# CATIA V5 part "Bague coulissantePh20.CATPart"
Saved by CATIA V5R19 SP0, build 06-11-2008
Part number: Bague coulissante
Bounding box of the stored display mesh (mm): x -22.5 to 22.5, y -22.5 to 22.5, z 0 to 25
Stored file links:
  C:\Users\Laurent\Desktop\Sujet Bac national\Sujet National E33\CFAO Catia\Bague coulissantePh20.CATPart
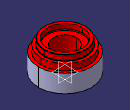
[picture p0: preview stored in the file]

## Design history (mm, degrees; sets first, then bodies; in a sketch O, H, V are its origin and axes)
Body1 (main body)
  Sketch1 on xy-plane, origin (0, 0, 0), H (1, 0, 0), V (0, 1, 0)
    circle A1 centre (0, 0) radius 22.5
    radius A1 = 22.5
  Pad1: profile Sketch1, direction (0, 0, 1), length 25
  Sketch2 on end face of Pad1, origin (0, 0, 25), H (1, 0, 0), V (0, 1, 0)
    circle A1 centre (0, 0) radius 17.45
    radius A1 = 17.45
  Pocket1: profile Sketch2, direction (0, 0, -1), length 4.78, outer side
  Sketch3 on end face of Pad1, origin (0, 0, 25), H (1, 0, 0), V (0, 1, 0)
    circle A1 centre (0, 0) radius 20
    radius A1 = 20
  Pocket2: profile Sketch3, direction (0, 0, -1), length 10, outer side
  Sketch4 on end face of Pad1, origin (0, 0, 25), H (1, 0, 0), V (0, 1, 0)
    circle A1 centre (0, 0) radius 10
    radius A1 = 10
  Pocket3: profile Sketch4, direction (0, 0, -1), through (limit type 3)
  Sketch5 on end face of Pad1, origin (0, 0, 25), H (1, 0, 0), V (0, 1, 0)
    circle A1 centre (0, 0) radius 14.95
    radius A1 = 14.95
  Pocket4: profile Sketch5, direction (0, 0, -1), length 4.78
  Sketch6 on zx-plane, origin (0, 0, 0), H (-1, 0, 0), V (0, 0, 1)
    axis line L1 (-25.6583, 20.6) -> (32.7674, 20.6)
    arc A1 centre (14.79, 20.6) radius 0.5 from (14.79, 20.1) to (14.79, 21.1) ccw
    point P3 (14.79, 20.6)
    reference projected line E1 (-17.45, 25) -> (17.45, 25) from edge [face of Pocket1 from Sketch2.A1 | end face of Pad1]
    line L2 (14.79, 20.1) -> (0, 20.1)
    point P4 (0, 20.1)
    line L3 (14.79, 21.1) -> (0, 21.1)
    point P5 (0, 21.1)
    line L4 (0, 20.1) -> (0, 21.1)
    reference projected line E2 through (0, 0) direction (0, 1) from axis of face of Pocket1 from Sketch2.A1
    distance L1 E1 = 4.4
    radius A1 = 0.5
    distance A1 E2 = 15.29
    horizontal: L1 H, L2 H, L3 H
    coincidence: P3 L1, P4 V, P5 V
    tangency: L3 A1, L2 A1
    vertical: L4 V
  Groove1: profile Sketch6, axis axis of face of Pocket2 from Sketch3.A1, angle 360
  Fillet1: radius 0.3, on edge [face of Pocket1 from Sketch2.A1 | end face of Pad1]; edge [end face of Pocket1 | face of Pocket1 from Sketch2.A1]
  Sketch7 on start face of Pad1, origin (0, 0, 0), H (1, 0, 0), V (0, -1, 0)
    circle A1 centre (0, 0) radius 23.7695
  Pocket5: profile Sketch7, direction (0, 0, 1), length 1.42, deactivated
  Sketch8 on end face of Pocket5, origin (0, 0, 1.42), H (1, 0, 0), V (0, -1, 0)
    circle A1 centre (0, 0) radius 17.9915
    radius A1 = 17.9915
  Pocket6: profile Sketch8, direction (0, 0, 1), length 14.8, outer side, deactivated
  Sketch9 on end face of Pocket5, origin (0, 0, 1.42), H (1, 0, 0), V (0, -1, 0)
    circle A1 centre (0, 0) radius 16.5
    radius A1 = 16.5
  Pocket7: profile Sketch9, direction (0, 0, 1), length 6.8, outer side, deactivated
  Chamfer1: length 1.5, angle 45, on edge [face of Pocket7 from Sketch9.A1 | end face of Pocket5], deactivated
  Sketch10 on zx-plane, origin (0, 0, 0), H (-1, 0, 0), V (0, 0, 1)
    line L1 (15.5, 8.22) -> (15.5, 6.72)
    line L2 (15.5, 6.72) -> (31.9529, 6.72)
    line L3 (15.5, 8.22) -> (31.9529, 8.22)
    line L4 (31.9529, 8.22) -> (31.9529, 6.72)
    reference projected line E1 (14.5, 1.42) -> (-14.5, 1.42) from edge [face of Chamfer1 | end face of Pocket5]
    reference projected line E2 through (0, 0) direction (0, -1) from axis of face of Pocket7 from Sketch9.A1
    distance L3 E1 = 6.8
    distance L1 E2 = 15.5
    distance L3 L2 = 1.5
    vertical: L1 V, L4 V
    horizontal: L2 H, L3 H
  Groove2: profile Sketch10, axis axis of face of Chamfer1, angle 360, deactivated
  Fillet2: radius 0.5, on edge [face of Groove2 from Sketch10.L1 | face of Groove2]; edge [face of Groove2 from Sketch10.L2 | face of Groove2 from Sketch10.L1], deactivated
  Sketch11 on end face of Pocket5, origin (0, 0, 1.42), H (1, 0, 0), V (0, -1, 0)
    circle A1 centre (0, 0) radius 14.2912
    radius A1 = 14.2912
  Pocket8: profile Sketch11, direction (0, 0, -1), through (limit type 3), deactivated
  Chamfer2: length 0.9, angle 30, on edge [end face of Pocket5 | face of Pocket8 from Sketch11.A1], deactivated
  Plane1: type Offset, Offset 19, RefPlane yz-plane
  Sketch12 on Plane1, origin (19, 0, 0), H (0, 1, 0), V (0, 0, 1)
    line L1 (-10, 18.22) -> (10, 18.22)
    line L2 (10, 18.22) -> (10, 14.8867)
    line L3 (10, 14.8867) -> (-10, 14.8867)
    line L4 (-10, 14.8867) -> (-10, 18.22)
    reference projected line E1 (20, 16.22) -> (-20, 16.22) from edge [face of Pocket2 from Sketch3.A1 | end face of Pocket6]
    reference projected line E2 through (0, 0) direction (0, -1) from axis of face of Pocket6 from Sketch8.A1
    reference projected line E3 through (0, 0) direction (0, -1) from axis of face of Pocket6 from Sketch8.A1
    distance L1 E1 = 2
    distance L2 E2 = 10
    distance L4 E3 = 10
    horizontal: L1 H, L3 H
    vertical: L2 V, L4 V
  Pocket9: profile Sketch12, direction (1, 0, 0), through (limit type 3), deactivated
  Mirror1: of Pocket9, about yz-plane, deactivated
